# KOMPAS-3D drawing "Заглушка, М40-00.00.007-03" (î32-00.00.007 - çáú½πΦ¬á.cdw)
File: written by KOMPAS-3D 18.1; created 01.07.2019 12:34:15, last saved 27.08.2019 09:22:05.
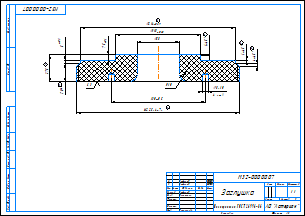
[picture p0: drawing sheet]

Sheet 1: A3, landscape

Document properties: Организация: Астерион; Полное имя файла: D:\Magna\Магна Ins\Магна ins 32\Для Караби\М32-00.00.007 - Заглушка.cdw

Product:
- Part/product: Заглушка  | designation М40-00.00.007-03
    Масса: 8.03373
    source file: М40-00.00.007 - Заглушка.cdw
- Part/product: Заглушка  | designation М40-00.00.007-02
    Масса: 8.60848
- Part/product: Деталь  | designation М40-00.00.007
    Масса: 7.02731
- Part/product: Заглушка  | designation М40-00.00.007-01
    Масса: 9.35455
- Part/product: Заглушка  | designation М32-00.00.007М32
    Масса: 8.94851
    source file: ..\М32-00.00.007 - Заглушка.cdw
- Part/product: Заглушка ПВХ  | designation М40-10.00.007-ПВХ
    Масса: 4.70059
- Part/product: Косячная (удолить)  | designation М40-00.00.007-6666
    Масса: 8.81523
    source file: М40-00.00.007-06 - Заглушка.cdw

Title block, sheet 1: Наименование: Заглушка; designation: М32-00.00.007; Материал: Полипропилен ГОСТ 26996-86; scale: 1:1; Количество листов документа: 1; organisation: АО "Астерион"; Форматы листов документа: A3; stored path: D:\Magna\Магна Ins\Магна ins 40\3Д\М40-00.00.007-02 - Заглушка.cdw; Разработал: Лифлянд; Проверил: Борисенко; Утвердил: Григорьева

Views: Вид 1, Местный разрез 1, Снизу
Referenced files in D:\Magna\Магна Ins\Магна ins 32\Для Караби\: М40-00.00.007-01 - Заглушка.m3d
Referenced files in D:\Magna\Магна Ins\Магна ins 40\3Д\: М40-00.00.007-01 - Заглушка.m3d
Dimensions and other numbers on the sheet: 225; 130±0,5; 10; 8; 4 отв.; 37,5; 25; 5; 7,5; 118; 58; 214; 4; 6,3; 1; 2; 1:1; 12.07.2019; 27.08.2019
